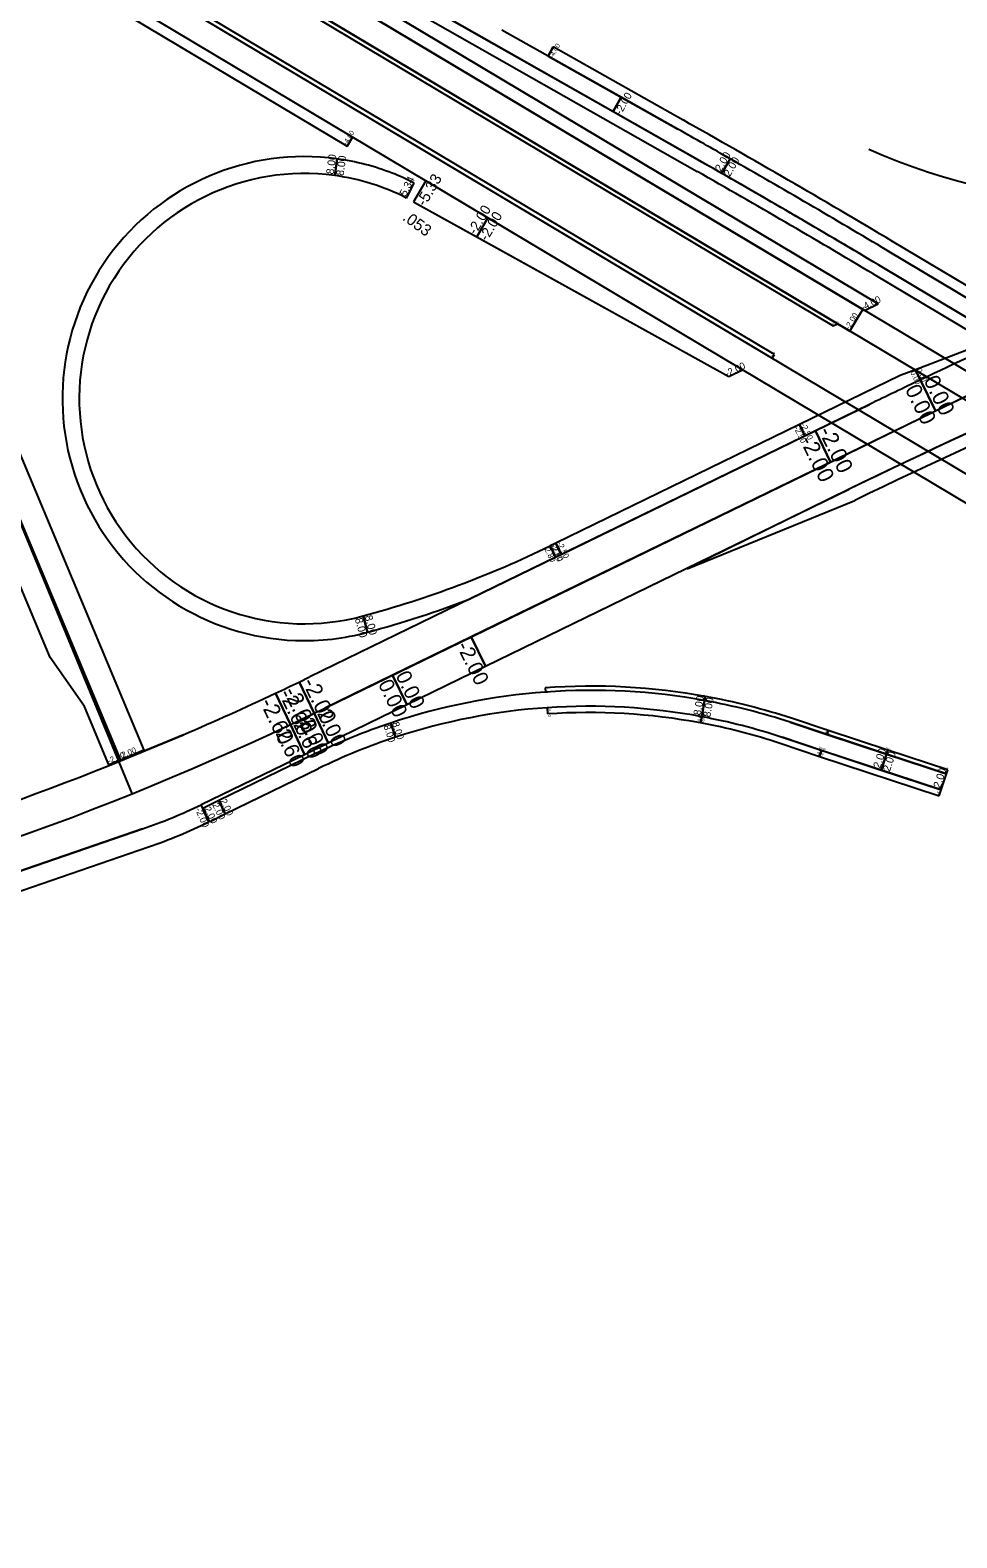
# Model space of a CAD drawing. Extents: x 2342222 to 2351711, y 366548 to 372860.
# Drawn here: x 2348514 to 2349395, y 366977 to 368410 of the extents above; entities that cross this region are included whole.
import ezdxf

# ---------------------------------------------------------------- set-up
doc = ezdxf.new("R2010")
doc.units = 0
for name, color, linetype in [('RD_HC_Cl', 7, 'Continuous'), ('RD_PD_Final_LnLine', 7, 'Continuous'), ('RD_PD_PaveShd', 7, 'Continuous'), ('RD_PD_SuperShp_BL_EB_526', 7, 'Continuous'), ('RD_PD_SuperShp_BL_WB_526', 7, 'Continuous'), ('RD_PD_SuperShp_REL_LINE-3', 7, 'Continuous'), ('RD_PD_SuperShp_Rel_Line-4', 7, 'Continuous'), ('RD_PD_SUPERSHP_REL_LINE-5', 7, 'Continuous'), ('RD_PD_SuperShp_REL_LINE-6', 7, 'Continuous'), ('RD_PD_SuperShp_S-97', 7, 'Continuous'), ('RD_PD_SuperShp_WB_526', 7, 'Continuous')]:
    doc.layers.add(name, color=color, linetype=linetype)

msp = doc.modelspace()

# ---------------------------------------------------------------- linework, layer by layer
at = {"layer": 'RD_HC_Cl'}
msp.add_arc((2349555.5, 368844.5), 600, 245.9774, 292.0147, dxfattribs=at)
msp.add_arc((2349555.5, 368844.5), 600, 245.9774, 292.0147, dxfattribs=at)
at = {"layer": 'RD_PD_Final_LnLine'}
msp.add_line((2348611, 367683.9), (2348357, 368298.5), dxfattribs=at)
msp.add_line((2348611, 367683.9), (2348357, 368298.5), dxfattribs=at)
at = {"layer": 'RD_PD_PaveShd'}
for p, q in [((2348633, 368559.4), (2349320.1, 368149.4)), ((2348612.7, 368524.9), (2349277.3, 368128.4)), ((2349307.2, 368143.1), (2349320.1, 368149.4)), ((2349277.3, 368128.4), (2349281.6, 368130.5))]:
    msp.add_line(p, q, dxfattribs=at)
at = {"layer": 'RD_PD_SuperShp_BL_EB_526'}
for p, q in [((2349221.6, 368101.1), (2348586.1, 368480.2)), ((2348584, 368476.8), (2351064, 366997.1)), ((2348584, 368476.8), (2349219.5, 368097.6)), ((2348552.3, 368456.1), (2348815.4, 368299.2)), ((2351051.7, 366976.5), (2348571.6, 368456.3)), ((2348820.5, 368307.8), (2348571.6, 368456.3)), ((2348820.5, 368307.8), (2348815.4, 368299.2)), ((2348815.4, 368299.2), (2348820.5, 368307.8)), ((2348890.1, 368266.2), (2348878.4, 368246.5)), ((2348890.1, 368266.2), (2348878.4, 368246.5)), ((2348949.1, 368231), (2348890.1, 368266.2)), ((2348878.4, 368246.5), (2349178.3, 368080.3)), ((2348878.4, 368246.5), (2348938.5, 368213.2)), ((2348938.5, 368213.2), (2348949.1, 368231)), ((2348949.1, 368231), (2348938.5, 368213.2)), ((2349191.2, 368086.6), (2348949.1, 368231)), ((2348938.5, 368213.2), (2349178.3, 368080.3)), ((2349219.5, 368097.6), (2349221.6, 368101.1)), ((2349178.3, 368080.3), (2349191.2, 368086.6)), ((2349178.3, 368080.3), (2349191.2, 368086.6))]:
    msp.add_line(p, q, dxfattribs=at)
at = {"layer": 'RD_PD_SuperShp_BL_WB_526'}
for p, q in [((2349320.1, 368149.4), (2348633, 368559.4)), ((2350982.8, 367143.5), (2348626.9, 368549)), ((2348626.9, 368549), (2349307.2, 368143.1)), ((2348612.7, 368524.9), (2349277.3, 368128.4)), ((2348614.8, 368528.3), (2350970.5, 367122.8)), ((2349281.6, 368130.5), (2348614.8, 368528.3)), ((2349307.2, 368143.1), (2349320.1, 368149.4)), ((2349277.3, 368128.4), (2349281.6, 368130.5))]:
    msp.add_line(p, q, dxfattribs=at)
at = {"layer": 'RD_PD_SuperShp_REL_LINE-3'}
for p, q in [((2348374.4, 368254.5), (2348599.8, 367715.8)), ((2348599.8, 367715.8), (2348409.1, 368171.5)), ((2348622, 367725.1), (2348599.8, 367715.8)), ((2348599.8, 367715.8), (2348588.8, 367711.2))]:
    msp.add_line(p, q, dxfattribs=at)
for points in [[(2348588.8, 367711.2), (2348565.6, 367766.6), (2348533.1, 367813.2), (2348496.6, 367900.3), (2348363.3, 368249.9)], [(2348423.9, 368177.7), (2348478.3, 368068.3), (2348622, 367725.1)]]:
    msp.add_lwpolyline(points, dxfattribs=at)
at = {"layer": 'RD_PD_SuperShp_Rel_Line-4'}
for p, q in [((2348955.1, 368396.3), (2348521.8, 368642.3)), ((2349153, 368283.9), (2348521.8, 368642.3)), ((2348521.8, 368642.3), (2348955.1, 368396.3)), ((2348516.8, 368633.6), (2349148.1, 368275.2)), ((2349075.8, 368345.8), (2348962.5, 368409.5)), ((2349153, 368283.9), (2348955.1, 368396.3)), ((2348955.1, 368396.3), (2349068.1, 368332.1)), ((2349006.3, 368384.9), (2349011.2, 368393.6)), ((2349011.2, 368393.6), (2349006.3, 368384.9)), ((2349134.7, 368324.1), (2349011.2, 368393.6)), ((2349006.3, 368384.9), (2349129.8, 368315.4)), ((2349068.1, 368332.1), (2349075.8, 368345.8)), ((2349075.8, 368345.8), (2349068.1, 368332.1)), ((2349129.8, 368315.4), (2349075.8, 368345.8)), ((2349068.1, 368332.1), (2349068.1, 368332.1)), ((2349068.1, 368332.1), (2349153, 368283.9)), ((2349179.5, 368287.3), (2349171.5, 368273.4)), ((2349171.5, 368273.4), (2349179.5, 368287.3)), ((2349753.1, 367958.6), (2349333.9, 368208.7)), ((2349328.8, 368200.1), (2349747.9, 367950)), ((2349747.9, 367950), (2349328.8, 368200.1)), ((2349328.8, 368200.1), (2349747.9, 367950)), ((2349320.6, 368186.4), (2349739.7, 367936.3)), ((2349689.1, 367966.5), (2349320.6, 368186.4)), ((2349320.6, 368186.4), (2349739.7, 367936.3)), ((2349315.5, 368177.8), (2349683.9, 367957.9))]:
    msp.add_line(p, q, dxfattribs=at)
for radius, start, end in [(9010, 59.17851, 60.64281), (9000, 60.27945, 60.64281), (9000, 60.27945, 60.64281), (8984, 59.17851, 60.4151), (8984, 60.27951, 60.4151), (9000, 59.17851, 60.27945), (9000, 59.17851, 60.27945), (8974, 59.17851, 60.4151), (8984, 59.17851, 60.27945)]:
    msp.add_arc((2344717.5, 360471.2), radius, start, end, dxfattribs=at)
at = {"layer": 'RD_PD_SUPERSHP_REL_LINE-5'}
for p, q in [((2349003.7, 367784.4), (2349004, 367780.4)), ((2349005.4, 367765.6), (2349005.8, 367759.6)), ((2349152.4, 367757), (2349155.1, 367772.4)), ((2349155.1, 367772.4), (2349152.4, 367757)), ((2349155.8, 367776.3), (2349155.1, 367772.4)), ((2349155.1, 367772.4), (2349155.8, 367776.3)), ((2348861.4, 367737.5), (2348856.9, 367751)), ((2348856.9, 367751), (2348861.4, 367737.5)), ((2349151.3, 367751.1), (2349152.4, 367757)), ((2349152.4, 367757), (2349151.3, 367751.1)), ((2349236.6, 367751.7), (2349271.4, 367740.2)), ((2349328, 367721.5), (2349236.6, 367751.7)), ((2349272.6, 367744), (2349237.8, 367755.5)), ((2349228.8, 367737.4), (2349323, 367706.3)), ((2349266.4, 367725), (2349228.8, 367737.4)), ((2349271.4, 367740.2), (2349272.6, 367744)), ((2349272.6, 367744), (2349271.4, 367740.2)), ((2349271.4, 367740.2), (2349328, 367721.5)), ((2349329.3, 367725.3), (2349272.6, 367744)), ((2348783.9, 367721.3), (2348693.3, 367677.2)), ((2349227, 367731.7), (2349264.5, 367719.3)), ((2349264.5, 367719.3), (2349266.4, 367725)), ((2349266.4, 367725), (2349264.5, 367719.3)), ((2349264.5, 367719.3), (2349378.2, 367681.8)), ((2349380.1, 367687.5), (2349266.4, 367725)), ((2349328, 367721.5), (2349323, 367706.3)), ((2349323, 367706.3), (2349328, 367721.5)), ((2349328, 367721.5), (2349329.3, 367725.3)), ((2349329.3, 367725.3), (2349328, 367721.5)), ((2349328, 367721.5), (2349385.1, 367702.7)), ((2349385.1, 367702.7), (2349328, 367721.5)), ((2349386.4, 367706.5), (2349329.3, 367725.3)), ((2348699.4, 367664.6), (2348788.2, 367707.8)), ((2349323, 367706.3), (2349380.1, 367687.5)), ((2349385.1, 367702.7), (2349386.4, 367706.5)), ((2349380.1, 367687.5), (2349385.1, 367702.7)), ((2348693.3, 367677.2), (2348678.2, 367669.8)), ((2348699.4, 367664.6), (2348693.3, 367677.2)), ((2348693.3, 367677.2), (2348699.4, 367664.6)), ((2349378.2, 367681.8), (2349380.1, 367687.5)), ((2348678.2, 367669.8), (2348684.3, 367657.2)), ((2348684.3, 367657.2), (2348699.4, 367664.6))]:
    msp.add_line(p, q, dxfattribs=at)
for centre, radius, start, end in [((2349047.7, 367179), 603, 94.1629, 108.4537), ((2349047.7, 367179), 607, 79.7395, 94.1629), ((2349047.7, 367179), 603, 79.7395, 94.1629), ((2349047.7, 367179), 603, 79.7395, 94.1629), ((2349045, 367179.9), 587, 93.8715, 108.2291), ((2349045, 367179.9), 587, 79.4622, 93.8715), ((2349045, 367179.9), 587, 79.4622, 93.8715), ((2349047.7, 367179), 603, 71.7499, 79.7395), ((2349047.7, 367179), 603, 71.7499, 79.7395), ((2349047.7, 367179), 607, 71.7499, 79.7395), ((2349047.7, 367179), 603, 108.4537, 115.9407), ((2349045, 367179.9), 581, 79.4622, 93.8715), ((2349045, 367179.9), 581, 71.7499, 79.4622), ((2349045, 367179.9), 587, 71.7499, 79.4622), ((2349045, 367179.9), 587, 71.7499, 79.4622), ((2349045, 367179.9), 587, 108.2291, 115.9407)]:
    msp.add_arc(centre, radius, start, end, dxfattribs=at)
at = {"layer": 'RD_PD_SuperShp_REL_LINE-6'}
for p, q in [((2348803.5, 368271.3), (2348805.7, 368287.2)), ((2348805.7, 368287.2), (2348803.5, 368271.3)), ((2348871.9, 368249.9), (2348879.2, 368264.2)), ((2348932.1, 367869), (2349013.5, 367908.6)), ((2349013.5, 367908.6), (2349008.3, 367919.4)), ((2348830.6, 367852.8), (2348834.8, 367837.3)), ((2348834.8, 367837.3), (2348830.6, 367852.8))]:
    msp.add_line(p, q, dxfattribs=at)
for centre, radius, start, end in [((2348774.6, 368059.3), 230, 82.2483, 267.9014), ((2348774.6, 368059.3), 230, 68.6661, 82.2483), ((2348774.6, 368059.3), 214, 82.2482, 285.1604), ((2348774.6, 368059.3), 214, 62.9736, 82.2482), ((2348774.6, 368059.3), 230, 62.9738, 68.6661), ((2348566.5, 368827.6), 1010, 285.1612, 295.9407), ((2348566.5, 368827.6), 1026, 285.1616, 290.8797), ((2348774.6, 368059.3), 230, 268.0448, 285.1608), ((2348795.3, 368069.4), 241.7, 263.0856, 263.2226)]:
    msp.add_arc(centre, radius, start, end, dxfattribs=at)
at = {"layer": 'RD_PD_SuperShp_S-97'}
for p, q in [((2349460.1, 368126.5), (2349355.7, 368086.8)), ((2349441.5, 368080), (2348933.2, 367832.8)), ((2349341.1, 368081.2), (2349245.4, 368034.7)), ((2349355.7, 368086.8), (2349341.1, 368081.2)), ((2349355.7, 368086.8), (2349360.4, 368077)), ((2349360.4, 368077), (2349355.7, 368086.8)), ((2349374.8, 368047.6), (2349441.5, 368080)), ((2349374.8, 368047.6), (2349360.4, 368077)), ((2349360.4, 368077), (2349374.8, 368047.6)), ((2349250.6, 368023.9), (2349312, 368053.8)), ((2349312, 368053.8), (2349260.5, 368028.7)), ((2349245.4, 368034.7), (2349013.7, 367922)), ((2349245.4, 368034.7), (2349250.6, 368023.9)), ((2349250.6, 368023.9), (2349245.4, 368034.7)), ((2349274.9, 367999), (2349374.8, 368047.6)), ((2349260.5, 368028.7), (2348779.7, 367794.8)), ((2349018.9, 367911.2), (2349250.6, 368023.9)), ((2349274.9, 367999), (2349260.5, 368028.7)), ((2349260.5, 368028.7), (2349274.9, 367999)), ((2348794.1, 367765.1), (2349274.9, 367999)), ((2348946.8, 367804.9), (2349292.7, 367973.2)), ((2349292.7, 367973.2), (2349138.6, 367897.6)), ((2349138.6, 367897.6), (2349298, 367962.4)), ((2349013.7, 367922), (2349008.3, 367919.4)), ((2349013.7, 367922), (2349018.9, 367911.2)), ((2349018.9, 367911.2), (2349013.7, 367922)), ((2349008.3, 367919.4), (2349013.5, 367908.6)), ((2349013.5, 367908.6), (2349018.9, 367911.2)), ((2348933.2, 367832.8), (2348858.6, 367796.5)), ((2348946.8, 367804.9), (2348933.2, 367832.8)), ((2348933.2, 367832.8), (2348946.8, 367804.9)), ((2348858.6, 367796.5), (2348794.1, 367765.1)), ((2348858.6, 367796.5), (2348872.2, 367768.6)), ((2348872.2, 367768.6), (2348858.6, 367796.5)), ((2348872.2, 367768.6), (2348946.8, 367804.9)), ((2348761.4, 367749.5), (2348747.3, 367779.3)), ((2348747.3, 367779.3), (2348761.4, 367749.5)), ((2348783.9, 367760.2), (2348769.6, 367790)), ((2348769.6, 367790), (2348783.9, 367760.2)), ((2348797.4, 367732.3), (2348872.2, 367768.6)), ((2348774.7, 367721.2), (2348761.4, 367749.5)), ((2348761.4, 367749.5), (2348774.7, 367721.2)), ((2348797.4, 367732.3), (2348783.9, 367760.2)), ((2348783.9, 367760.2), (2348797.4, 367732.3)), ((2348589, 367710.6), (2348659.6, 367739.8)), ((2348659.6, 367739.8), (2348589, 367710.6)), ((2348676.4, 367673.4), (2348774.7, 367721.2)), ((2348774.7, 367721.2), (2348797.4, 367732.3)), ((2348678.2, 367669.8), (2348676.4, 367673.4)), ((2348683.7, 367656.9), (2348678.2, 367669.8)), ((2348482.6, 367602.8), (2348620.6, 367650.3)), ((2348620.6, 367650.3), (2348482.6, 367602.8)), ((2348488.5, 367585.8), (2348626.5, 367633.3))]:
    msp.add_line(p, q, dxfattribs=at)
for centre, radius, start, end in [((2351783.3, 362853.3), 5693.6, 109.588, 115.9407), ((2351783.3, 362853.3), 5693.6, 111.0959, 115.9407), ((2351783.3, 362853.3), 5681.6, 111.0921, 115.9407), ((2351828.9, 362879.9), 5753.6, 114.29817, 115.40572), ((2351828.9, 362879.9), 5753.6, 114.29817, 115.40572), ((2351828.9, 362879.9), 5753.6, 115.40572, 115.94073), ((2351828.9, 362879.9), 5753.6, 115.40572, 115.94073), ((2347533.9, 370355.7), 2847.8, 295.7163, 295.9407), ((2347533.9, 370355.7), 2847.8, 293.2834, 295.2191), ((2347533.9, 370355.7), 2847.8, 295.2191, 295.7163), ((2347533.9, 370355.7), 2880.8, 295.7163, 295.9407), ((2347533.9, 370355.7), 2880.8, 295.7163, 295.9407), ((2347533.9, 370355.7), 2880.8, 282.1521, 295.2191), ((2347533.9, 370355.7), 2880.8, 282.1521, 295.2191), ((2347533.9, 370355.7), 2880.8, 295.2191, 295.7163), ((2347533.9, 370355.7), 2880.8, 295.2191, 295.7163), ((2347533.9, 370355.7), 2847.8, 282.1521, 291.7462), ((2348457.7, 368123), 500, 289.0148, 295.9407), ((2348457.7, 368123), 500, 289.0148, 295.9407), ((2348457.7, 368123), 518, 289.0148, 295.8624)]:
    msp.add_arc(centre, radius, start, end, dxfattribs=at)
at = {"layer": 'RD_PD_SuperShp_WB_526'}
for p, q in [((2346189.9, 369975), (2349293.2, 368123.5)), ((2349293.2, 368123.5), (2349305.5, 368144.1)), ((2349299.4, 368133.8), (2349305.6, 368144.1))]:
    msp.add_line(p, q, dxfattribs=at)
msp.add_lwpolyline([(2349305.5, 368144.1), (2347116.8, 369450), (2347110.7, 369439.7), (2346196.1, 369985.3)], dxfattribs=at)

# ---------------------------------------------------------------- texts
at = {"layer": 'RD_PD_SuperShp_BL_EB_526'}
for s, height, rotation, p in [('-4.00', 4.6, 59.1785, (2348815, 368299.9)), ('-5.33', 10.56, 59.1753, (2348889.4, 368241.2)), ('-2.00', 9.55, 59.1785, (2348937.6, 368214.5)), ('-2.00', 9.55, 59.1785, (2348948.4, 368208.4)), ('.053', 11.04, 324.0934, (2348867.2, 368229.7)), ('-2.00', 6.61, 25.8355, (2349176.5, 368079.7)), ('-2.00', 1.84, 59.1171, (2349219.4, 368097.9))]:
    msp.add_text(s, height=height, rotation=rotation, dxfattribs=at).set_placement(p)
at = {"layer": 'RD_PD_SuperShp_BL_WB_526'}
for s, height, p in [('-4.00', 6.58, (2349305.5, 368142.6)), ('-2.00', 2.19, (2349276.7, 368128.2))]:
    msp.add_text(s, height=height, rotation=26.2156, dxfattribs=at).set_placement(p)
at = {"layer": 'RD_PD_SuperShp_REL_LINE-3'}
for p in [(2348588.9, 367712.2), (2348599.9, 367716.8)]:
    msp.add_text('-2.00', height=5.52, rotation=22.7108, dxfattribs=at).set_placement(p)
at = {"layer": 'RD_PD_SuperShp_Rel_Line-4'}
for s, height, rotation, p in [('-4.00', 4.6, 60.6428, (2349011.1, 368382.6)), ('-2.00', 7.21, 60.6428, (2349075.7, 368328.6)), ('2.00', 7.36, 60.2794, (2349170.9, 368274.5)), ('2.00', 7.36, 60.2794, (2349179.2, 368269.7))]:
    msp.add_text(s, height=height, rotation=rotation, dxfattribs=at).set_placement(p)
at = {"layer": 'RD_PD_SUPERSHP_REL_LINE-5'}
for s, height, rotation, p in [('8.00', 1.84, 274.1629, (2349004, 367784.3)), ('8.00', 7.18, 79.7395, (2349151.4, 367757.8)), ('8.00', 1.84, 79.7395, (2349154.9, 367772.6)), ('8.00', 1.84, 79.7395, (2349157.3, 367772.2)), ('-8.00', 2.76, 273.8715, (2349005.8, 367765.4)), ('8.00', 7.18, 79.7395, (2349160.6, 367756.1)), ('8.00', 6.57, 288.4537, (2348849.8, 367748.1)), ('8.00', 6.57, 288.4537, (2348858, 367750.8)), ('-8.00', 2.76, 79.4622, (2349150.9, 367751.4)), ('-8.00', 2.76, 79.4622, (2349154.4, 367750.8)), ('4.00', 1.84, 71.7499, (2349271.1, 367740.5)), ('4.00', 1.84, 71.7499, (2349273.4, 367739.7)), ('-4.00', 2.76, 71.7499, (2349264.1, 367719.7)), ('-4.00', 2.76, 71.7499, (2349267.6, 367718.6)), ('2.00', 7.36, 71.7499, (2349322.1, 367707.3)), ('2.00', 7.36, 71.7499, (2349331.3, 367704.3)), ('-4.00', 1.84, 71.7499, (2349327.8, 367721.8)), ('-4.00', 1.84, 71.7499, (2349330.1, 367721)), ('2.00', 7.36, 71.7499, (2349379.3, 367688.5)), ('-4.00', 1.84, 71.7499, (2349384.9, 367702.9)), ('-4.00', 2.76, 71.7499, (2349377.9, 367682.2)), ('2.00', 6.44, 295.9407, (2348694.4, 367677.1)), ('2.00', 6.44, 295.9407, (2348679.3, 367669.7)), ('2.00', 6.44, 295.9407, (2348686.9, 367673.4))]:
    msp.add_text(s, height=height, rotation=rotation, dxfattribs=at).set_placement(p)
at = {"layer": 'RD_PD_SuperShp_REL_LINE-6'}
for s, height, rotation, p in [('8.00', 7.36, 82.2507, (2348802.5, 368272.1)), ('8.00', 7.36, 82.2507, (2348812, 368270.8)), ('5.34', 7.36, 62.9771, (2348871.2, 368251)), ('2.80', 5.52, 295.9407, (2349002.8, 367916.1)), ('8.00', 7.36, 285.1651, (2348822.6, 367849.9)), ('8.00', 7.36, 285.1834, (2348831.9, 367852.4))]:
    msp.add_text(s, height=height, rotation=rotation, dxfattribs=at).set_placement(p)
at = {"layer": 'RD_PD_SuperShp_S-97'}
for s, height, rotation, p in [('0.00', 4.99, 295.9407, (2349350.6, 368084.2)), ('0.00', 4.99, 295.9407, (2349356.6, 368086.7)), ('0.00', 15.06, 295.9407, (2349363.1, 368076.9)), ('0.00', 15.06, 295.9407, (2349345.4, 368068.3)), ('-2.50', 5.52, 295.9407, (2349246.3, 368034.6)), ('-2.50', 5.52, 295.9407, (2349239.9, 368031.5)), ('-2.00', 15.18, 295.9407, (2349245.4, 368019.9)), ('-2.00', 15.18, 295.9407, (2349263.2, 368028.5)), ('-2.80', 5.52, 295.9407, (2349009.2, 367919.3)), ('-2.50', 5.52, 295.9407, (2349014.6, 367921.9)), ('-2.50', 5.52, 295.9407, (2349008.2, 367918.8)), ('-2.00', 14.26, 295.9407, (2348919, 367824.5)), ('-2.00', 15.18, 295.7163, (2348772.3, 367789.8)), ('0.00', 14.26, 295.9407, (2348844.4, 367788.2)), ('0.00', 14.26, 295.9407, (2348861.1, 367796.3)), ('-2.60', 15.18, 295.2191, (2348750, 367779.1)), ('-2.00', 15.18, 295.7163, (2348754.4, 367781.2)), ('-2.60', 15.18, 295.2191, (2348732.1, 367770.7)), ('2.00', 14.27, 295.7163, (2348786.4, 367760.1)), ('2.60', 14.37, 295.2191, (2348763.8, 367749.4)), ('2.00', 14.27, 295.7163, (2348769.7, 367751.9)), ('2.60', 14.37, 295.2191, (2348747, 367741.2)), ('-2.00', 6.45, 293.0589, (2348670.7, 367669))]:
    msp.add_text(s, height=height, rotation=rotation, dxfattribs=at).set_placement(p)
at = {"layer": 'RD_PD_SuperShp_WB_526'}
msp.add_text('-2.00', height=5.52, rotation=59.1785, dxfattribs=at).set_placement((2349292.8, 368124.4))
msp.add_text('-2.00', height=5.52, rotation=59.1785, dxfattribs=at).set_placement((2349292.8, 368124.4))

doc.saveas('drawing.dxf')
